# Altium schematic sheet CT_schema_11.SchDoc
size 274 x 160 mm
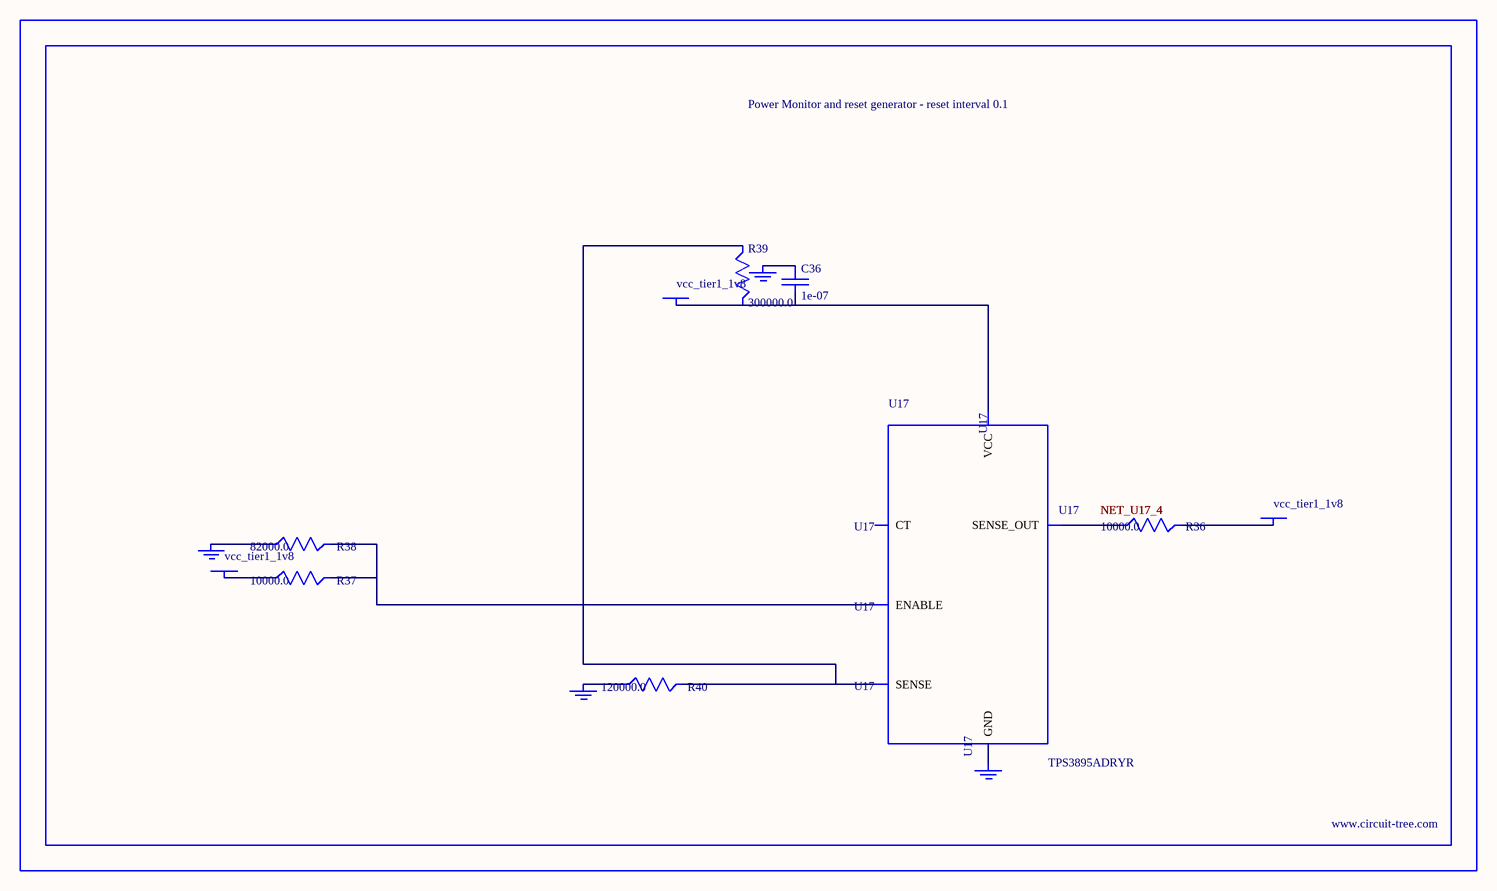
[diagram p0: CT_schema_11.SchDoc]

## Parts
BORDER10  (no value)
C36  1e-07  [C0402]
GND_INSTANCE_10_0  (no value)
GND_INSTANCE_10_1  (no value)
GND_INSTANCE_10_2  (no value)
GND_INSTANCE_10_3  (no value)
POWER_INSTANCE_10_0  vcc_tier1_1v8
POWER_INSTANCE_10_1  vcc_tier1_1v8
POWER_INSTANCE_10_2  vcc_tier1_1v8
R36  10000.0  [R0603]
R37  10000.0  [R0603]
R38  82000.0  [R0603]
R39  300000.0  [R0603]
R40  120000.0  [R0603]
U17  TPS3895ADRYR  [SON-6]

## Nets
NetC36_1: C36.1 GND_INSTANCE_10_2.0(GND)
NetC36_2: C36.2 POWER_INSTANCE_10_2.0(PWR) R39.2 U17.6(VCC)
NetGND_INSTANCE_10_0_0: GND_INSTANCE_10_0.0(GND) R38.1
NetGND_INSTANCE_10_1_0: GND_INSTANCE_10_1.0(GND) R40.1
NetGND_INSTANCE_10_3_0: GND_INSTANCE_10_3.0(GND) U17.2(GND)
NetPOWER_INSTANCE_10_0_0: POWER_INSTANCE_10_0.0(PWR) R37.1
NetPOWER_INSTANCE_10_1_0: POWER_INSTANCE_10_1.0(PWR) R36.2
NetR36_1: R36.1 U17.4(SENSE_OUT)
NetR37_2: R37.2 R38.2 U17.1(ENABLE)
NetR39_1: R39.1 R40.2 U17.3(SENSE)

Not connected (* = marked no-connect by the designer): U17 5(CT)

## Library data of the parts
BORDER10 = BORDER_PAGE10
C36 = C0402C104K3RACTU
GND_INSTANCE_10_0-GND_INSTANCE_10_3 = GND
POWER_INSTANCE_10_0-POWER_INSTANCE_10_2 = PWR
R36 R37 = RC0603JR-0710KL
R38 = RC0603JR-0782KL
R39 = RC0603JR-07300KL
R40 = RC0603JR-07120KL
